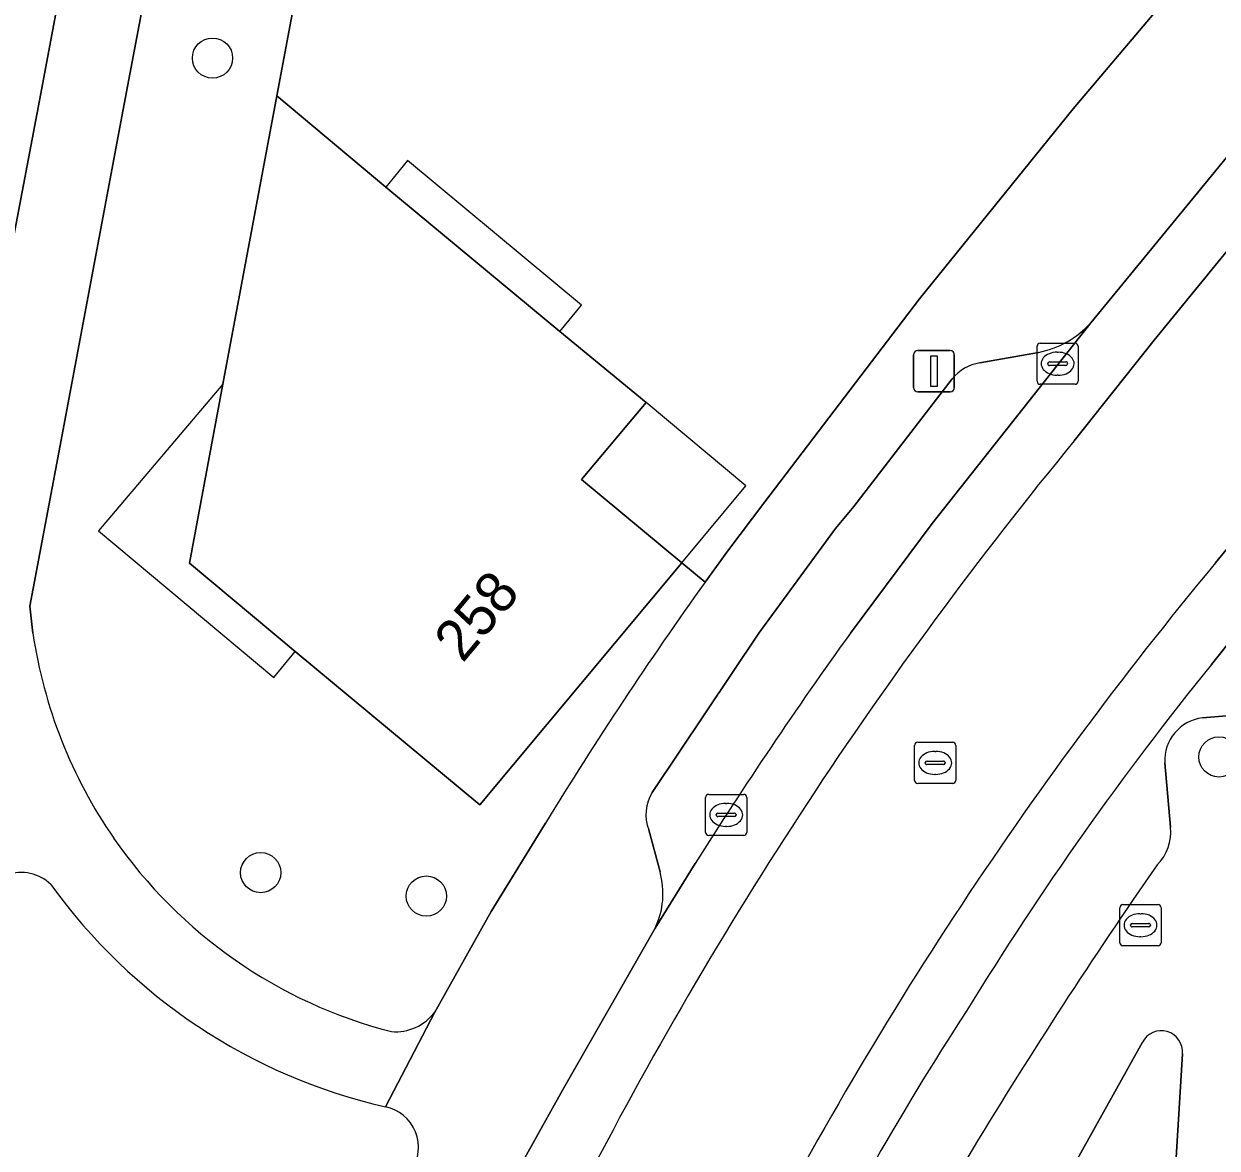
# Model space of a CAD drawing. Extents: x 160157 to 160921, y 381516 to 382045.
# Drawn here: x 160530.62 to 160559.64, y 381737.47 to 381764.83 of the extents above; entities that cross this region are included whole.
import ezdxf

# ---------------------------------------------------------------- set-up
doc = ezdxf.new("R2010")
doc.units = 0
for name, color, linetype in [('IMGEO_Boom', 7, 'Continuous'), ('IMGEO_Brandkraan', 7, 'Continuous'), ('IMGEO_Erf', 7, 'Continuous'), ('IMGEO_Groenvoorziening', 7, 'Continuous'), ('IMGEO_Kolk', 7, 'Continuous'), ('IMGEO_Lichtmast', 7, 'Continuous'), ('IMGEO_Muur', 7, 'Continuous'), ('IMGEO_Pand', 7, 'Continuous'), ('IMGEO_Pand_nummerreeks', 7, 'Continuous'), ('IMGEO_Pand_overbouw', 7, 'Continuous'), ('IMGEO_Parkeervlak_open', 7, 'Continuous'), ('IMGEO_Rijbaan_lokaal_gesloten', 7, 'Continuous'), ('IMGEO_Rijbaan_lokaal_open', 7, 'Continuous'), ('IMGEO_Rijbaan_regionaal_gesloten', 7, 'Continuous'), ('IMGEO_Rioolput', 7, 'Continuous'), ('IMGEO_Voetpad_open', 7, 'Continuous')]:
    doc.layers.add(name, color=color, linetype=linetype)

msp = doc.modelspace()

# ---------------------------------------------------------------- linework, layer by layer
at = {"layer": 'IMGEO_Boom'}
for centre in [(160535.206, 381763.995), (160559.686, 381746.988), (160536.378, 381744.173), (160540.407, 381743.603)]:
    msp.add_circle(centre, 0.489, dxfattribs=at)
at = {"layer": 'IMGEO_Brandkraan'}
for p, q in [((160557.276, 381742.468), (160557.276, 381743.32)), ((160557.351, 381743.394), (160558.203, 381743.394)), ((160558.277, 381743.32), (160558.277, 381742.468)), ((160557.764, 381743.174), (160557.789, 381743.174)), ((160557.535, 381742.888), (160557.535, 381742.9)), ((160557.973, 381742.851), (160557.575, 381742.851)), ((160557.578, 381742.937), (160557.976, 381742.937)), ((160558.019, 381742.9), (160558.019, 381742.888)), ((160557.787, 381742.614), (160557.762, 381742.614)), ((160558.203, 381742.394), (160557.351, 381742.394))]:
    msp.add_line(p, q, dxfattribs=at)
for points in [[(160557.276, 381742.468), (160557.276, 381743.32)], [(160557.351, 381743.394), (160558.203, 381743.394)], [(160558.277, 381743.32), (160558.277, 381742.468)], [(160558.203, 381742.394), (160557.351, 381742.394)]]:
    msp.add_lwpolyline(points, dxfattribs=at)
for centre, radius, start, end in [((160557.353, 381743.318), 0.0765, 91.552, 178.448), ((160557.353, 381743.318), 0.0765, 91.552, 178.448), ((160558.201, 381743.318), 0.0765, 1.552, 88.448), ((160558.201, 381743.318), 0.0765, 1.552, 88.448), ((160557.575, 381742.897), 0.0403, 85.8775, 175.7526), ((160557.572, 381742.887), 0.0366, 178.938, 274.7102), ((160557.976, 381742.894), 0.043, 264.8664, 352.4533), ((160557.98, 381742.899), 0.0386, 1.7309, 96.639), ((160557.353, 381742.47), 0.0765, 181.552, 268.448), ((160557.353, 381742.47), 0.0765, 181.552, 268.448), ((160558.201, 381742.47), 0.0765, 271.552, 358.448), ((160558.201, 381742.47), 0.0765, 271.552, 358.448)]:
    msp.add_arc(centre, radius, start, end, dxfattribs=at)
for centre, major_axis, ratio, start_param, end_param in [((160557.763, 381742.894), (-0.387, 0.002), 0.722429, 4.712389, 7.853982), ((160557.788, 381742.894), (-0.39, 0.002), 0.717154, 1.570796, 4.712389)]:
    msp.add_ellipse(centre, major_axis=major_axis, ratio=ratio, start_param=start_param, end_param=end_param, dxfattribs=at)
at = {"layer": 'IMGEO_Erf'}
msp.add_lwpolyline([(160539.559, 381777.945), (160536.769, 381763.076), (160539.423, 381760.856), (160543.658, 381757.346), (160545.757, 381755.618), (160544.18, 381753.74), (160546.621, 381751.714), (160547.187, 381751.244), (160547.737, 381752.007), (160548.643, 381753.199), (160552.4, 381758.139), (160556.143, 381762.763), (160556.812, 381763.555), (160559.232, 381766.417)], dxfattribs=at)
at = {"layer": 'IMGEO_Groenvoorziening'}
for points in [[(160537.22, 381749.558), (160534.647, 381751.702), (160535.455, 381756.063), (160536.769, 381763.076), (160539.559, 381777.945), (160538.044, 381779.218), (160536.414, 381780.659), (160535.155, 381773.997), (160533.001, 381762.573), (160531.549, 381754.827), (160530.76, 381750.659), (160530.838, 381750)], [(160547.187, 381751.244), (160546.621, 381751.714), (160541.708, 381745.82), (160537.22, 381749.558)], [(160540.611, 381740.781), (160541.983, 381743.231), (160543.304, 381745.379)], [(160557.825, 381740.047), (160556.011, 381736.788), (160556.763, 381736.375), (160556.207, 381735.389), (160555.472, 381735.795), (160553.785, 381732.792), (160551.845, 381729.26)], [(160558.374, 381732.854), (160558.795, 381739.761)]]:
    msp.add_lwpolyline(points, dxfattribs=at)
for centre, radius, start, end in [((160627.441, 381693.893), 98.64, 144.44965, 148.5362), ((160542.505, 381751.716), 11.792, 188.3662, 214.6331), ((160542.491, 381751.709), 11.777, 214.6422, 255.5732), ((160530.557, 381743.145), 1.03, 45.9388, 173.6939), ((160542.511, 381751.955), 13.835, 215.6825, 257.0609), ((160539.652, 381741.494), 1.195, 265.4295, 323.3601), ((160558.282, 381739.81), 0.515, 354.542, 152.6021), ((160539.22, 381737.493), 0.997, 325.0805, 78.8663)]:
    msp.add_arc(centre, radius, start, end, dxfattribs=at)
at = {"layer": 'IMGEO_Kolk'}
for p, q in [((160555.261, 381756.132), (160555.261, 381756.984)), ((160555.336, 381757.058), (160556.188, 381757.058)), ((160556.262, 381756.984), (160556.262, 381756.132)), ((160555.749, 381756.838), (160555.774, 381756.838)), ((160555.52, 381756.552), (160555.52, 381756.564)), ((160555.958, 381756.515), (160555.56, 381756.515)), ((160555.563, 381756.601), (160555.961, 381756.601)), ((160556.004, 381756.564), (160556.004, 381756.552)), ((160555.772, 381756.278), (160555.747, 381756.278)), ((160556.188, 381756.058), (160555.336, 381756.058)), ((160547.199, 381745.152), (160547.199, 381746.004)), ((160547.274, 381746.078), (160548.126, 381746.078)), ((160548.2, 381746.004), (160548.2, 381745.152)), ((160547.501, 381745.621), (160547.899, 381745.621)), ((160547.687, 381745.858), (160547.712, 381745.858)), ((160547.458, 381745.572), (160547.458, 381745.584)), ((160547.896, 381745.535), (160547.498, 381745.535)), ((160547.942, 381745.584), (160547.942, 381745.572)), ((160548.126, 381745.078), (160547.274, 381745.078)), ((160547.71, 381745.298), (160547.685, 381745.298))]:
    msp.add_line(p, q, dxfattribs=at)
for points in [[(160555.261, 381756.132), (160555.261, 381756.984)], [(160555.336, 381757.058), (160556.188, 381757.058)], [(160556.262, 381756.984), (160556.262, 381756.132)], [(160556.188, 381756.058), (160555.336, 381756.058)], [(160547.199, 381745.152), (160547.199, 381746.004)], [(160547.274, 381746.078), (160548.126, 381746.078)], [(160548.2, 381746.004), (160548.2, 381745.152)], [(160548.126, 381745.078), (160547.274, 381745.078)]]:
    msp.add_lwpolyline(points, dxfattribs=at)
for centre, radius, start, end in [((160555.338, 381756.982), 0.0765, 91.552, 178.448), ((160555.338, 381756.982), 0.0765, 91.552, 178.448), ((160556.186, 381756.982), 0.0765, 1.552, 88.448), ((160556.186, 381756.982), 0.0765, 1.552, 88.448), ((160555.56, 381756.561), 0.0403, 85.8775, 175.7526), ((160555.557, 381756.551), 0.0366, 178.938, 274.7102), ((160555.961, 381756.558), 0.043, 264.8664, 352.4533), ((160555.965, 381756.563), 0.0386, 1.7309, 96.639), ((160555.338, 381756.134), 0.0765, 181.552, 268.448), ((160555.338, 381756.134), 0.0765, 181.552, 268.448), ((160556.186, 381756.134), 0.0765, 271.552, 358.448), ((160556.186, 381756.134), 0.0765, 271.552, 358.448), ((160547.276, 381746.002), 0.0765, 91.552, 178.448), ((160547.276, 381746.002), 0.0765, 91.552, 178.448), ((160548.124, 381746.002), 0.0765, 1.552, 88.448), ((160548.124, 381746.002), 0.0765, 1.552, 88.448), ((160547.498, 381745.581), 0.0403, 85.8775, 175.7526), ((160547.903, 381745.583), 0.0386, 1.7309, 96.639), ((160547.495, 381745.571), 0.0366, 178.938, 274.7102), ((160547.899, 381745.578), 0.043, 264.8664, 352.4533), ((160547.276, 381745.154), 0.0765, 181.552, 268.448), ((160547.276, 381745.154), 0.0765, 181.552, 268.448), ((160548.124, 381745.154), 0.0765, 271.552, 358.448), ((160548.124, 381745.154), 0.0765, 271.552, 358.448)]:
    msp.add_arc(centre, radius, start, end, dxfattribs=at)
for centre, major_axis, ratio, start_param, end_param in [((160555.748, 381756.558), (-0.387, 0.002), 0.722429, 4.712389, 7.853982), ((160555.773, 381756.558), (-0.39, 0.002), 0.717154, 1.570796, 4.712389), ((160547.686, 381745.578), (-0.387, 0.002), 0.722429, 4.712389, 7.853982), ((160547.711, 381745.578), (-0.39, 0.002), 0.717154, 1.570796, 4.712389)]:
    msp.add_ellipse(centre, major_axis=major_axis, ratio=ratio, start_param=start_param, end_param=end_param, dxfattribs=at)
at = {"layer": 'IMGEO_Lichtmast'}
for p, q in [((160552.259, 381755.976), (160552.259, 381756.776)), ((160552.259, 381756.776), (160552.259, 381755.976)), ((160552.359, 381756.876), (160553.149, 381756.876)), ((160553.149, 381756.876), (160552.359, 381756.876)), ((160553.249, 381756.776), (160553.249, 381755.976)), ((160553.249, 381755.976), (160553.249, 381756.776)), ((160553.149, 381755.876), (160552.359, 381755.876)), ((160552.359, 381755.876), (160553.149, 381755.876))]:
    msp.add_line(p, q, dxfattribs=at)
msp.add_lwpolyline([(160552.679, 381756.751), (160552.829, 381756.751), (160552.829, 381756.001), (160552.679, 381756.001), (160552.679, 381756.751)], dxfattribs=at)
for centre, start, end in [((160552.359, 381756.776), 90, 180), ((160552.359, 381756.776), 90, 180), ((160553.149, 381756.776), 0, 90), ((160553.149, 381756.776), 360, 90), ((160552.359, 381755.976), 180, 270), ((160552.359, 381755.976), 180, 270), ((160553.149, 381755.976), 270, 0), ((160553.149, 381755.976), 270, 0)]:
    msp.add_arc(centre, 0.1, start, end, dxfattribs=at)
at = {"layer": 'IMGEO_Muur'}
msp.add_lwpolyline([(160539.559, 381777.945), (160536.769, 381763.076)], dxfattribs=at)
at = {"layer": 'IMGEO_Pand'}
msp.add_lwpolyline([(160543.658, 381757.346), (160539.423, 381760.856), (160536.769, 381763.076), (160535.455, 381756.063), (160534.647, 381751.702), (160537.22, 381749.558), (160541.708, 381745.82), (160546.621, 381751.714), (160544.18, 381753.74), (160545.757, 381755.618)], close=True, dxfattribs=at)
at = {"layer": 'IMGEO_Pand_overbouw'}
for points in [[(160539.423, 381760.856), (160543.658, 381757.346), (160544.179, 381757.981), (160539.946, 381761.505)], [(160537.22, 381749.558), (160534.647, 381751.702), (160535.455, 381756.063), (160532.435, 381752.487), (160536.695, 381748.923)], [(160546.621, 381751.714), (160548.178, 381753.589), (160545.757, 381755.618), (160544.18, 381753.74)]]:
    msp.add_lwpolyline(points, close=True, dxfattribs=at)
at = {"layer": 'IMGEO_Parkeervlak_open'}
for points in [[(160587.813, 381780.546), (160599.457, 381794.39), (160603.167, 381798.883), (160601.731, 381800.097), (160571.401, 381763.753), (160567.175, 381758.693), (160560.113, 381750), (160559.501, 381749.238)], [(160550.722, 381750), (160552.708, 381752.669), (160556.569, 381757.556)], [(160555.296, 381756.832), (160553.871, 381756.578)], [(160553.198, 381756.188), (160550.801, 381753.081), (160550.361, 381752.545), (160548.495, 381750), (160545.901, 381746.126)], [(160559.284, 381747.937), (160560.449, 381748.035)], [(160558.508, 381745.28), (160558.366, 381746.845)], [(160545.815, 381745.216), (160546.091, 381744.193)], [(160545.97, 381742.825), (160546.946, 381744.393)]]:
    msp.add_lwpolyline(points, dxfattribs=at)
for centre, radius, start, end in [((160554.856, 381759.087), 2.297, 281.0424, 318.2144), ((160554.037, 381755.516), 1.075, 98.8848, 141.2994), ((160638.25, 381686.98), 107.855, 144.24611, 147.83778), ((160621.002, 381699.491), 79.102, 141.03142, 148.50079), ((160559.408, 381746.901), 1.044, 96.8317, 183.0635), ((160546.801, 381745.582), 1.052, 148.8474, 200.3551), ((160557.409, 381745.154), 1.106, 314.2629, 6.5244), ((160544.229, 381743.668), 1.934, 334.1528, 15.7378), ((160665.269, 381669.95), 130.403, 145.20587, 148.81771), ((160616.65, 381699.761), 75.278, 146.94466, 153.91056), ((160642.221, 381685.451), 102.668, 149.55897, 154.04706)]:
    msp.add_arc(centre, radius, start, end, dxfattribs=at)
at = {"layer": 'IMGEO_Rijbaan_lokaal_gesloten'}
for points in [[(160556.164, 381754.68), (160558.112, 381757.129), (160560.755, 381760.365), (160581.539, 381785.212), (160597.19, 381803.934), (160596.045, 381804.906), (160595.807, 381805.107), (160595.401, 381804.621), (160589.126, 381797.112), (160588.465, 381796.32), (160588.699, 381796.124), (160587.352, 381794.513), (160562.011, 381764.214), (160561.758, 381763.877), (160556.569, 381757.556), (160552.708, 381752.669), (160550.722, 381750)], [(160559.501, 381749.238), (160560.113, 381750), (160567.175, 381758.693), (160571.401, 381763.753), (160601.731, 381800.097), (160600.729, 381800.991), (160582.713, 381779.526), (160568.843, 381763.002), (160559.601, 381751.709)], [(160546.946, 381744.393), (160545.97, 381742.825), (160543.709, 381738.866), (160540.908, 381733.824)]]:
    msp.add_lwpolyline(points, dxfattribs=at)
for centre, radius, start, end in [((160635.278, 381689.632), 102.422, 140.57288, 152.83712), ((160632.422, 381691.188), 94.687, 140.2702, 153.23003), ((160638.25, 381686.98), 107.855, 144.24611, 147.83778), ((160621.002, 381699.491), 79.102, 141.03142, 148.50079), ((160616.65, 381699.761), 75.278, 146.94466, 153.91056)]:
    msp.add_arc(centre, radius, start, end, dxfattribs=at)
at = {"layer": 'IMGEO_Rijbaan_lokaal_open'}
for points in [[(160568.843, 381763.002), (160582.713, 381779.526), (160600.729, 381800.991), (160597.19, 381803.934), (160581.539, 381785.212), (160560.755, 381760.365), (160558.112, 381757.129), (160556.164, 381754.68)], [(160559.601, 381751.709), (160568.843, 381763.002)]]:
    msp.add_lwpolyline(points, dxfattribs=at)
for centre, radius, start, end in [((160635.278, 381689.632), 102.422, 140.57288, 152.83712), ((160632.422, 381691.188), 94.687, 140.2702, 153.23003)]:
    msp.add_arc(centre, radius, start, end, dxfattribs=at)
at = {"layer": 'IMGEO_Rijbaan_regionaal_gesloten'}
msp.add_lwpolyline([(160528.299, 381748.554), (160528.561, 381750), (160529.214, 381753.603), (160531.031, 381763.137), (160531.658, 381766.473), (160532.282, 381769.787), (160534.195, 381779.861), (160534.361, 381783.239), (160534.845, 381787.255), (160535.72, 381795.222), (160536.596, 381803.188)], dxfattribs=at)
at = {"layer": 'IMGEO_Rioolput'}
for p, q in [((160552.283, 381746.418), (160552.283, 381747.27)), ((160552.358, 381747.344), (160553.21, 381747.344)), ((160552.771, 381747.124), (160552.796, 381747.124)), ((160553.284, 381747.27), (160553.284, 381746.418)), ((160552.542, 381746.838), (160552.542, 381746.85)), ((160552.98, 381746.801), (160552.582, 381746.801)), ((160552.585, 381746.887), (160552.983, 381746.887)), ((160553.026, 381746.85), (160553.026, 381746.838)), ((160552.794, 381746.564), (160552.769, 381746.564)), ((160553.21, 381746.344), (160552.358, 381746.344))]:
    msp.add_line(p, q, dxfattribs=at)
for points in [[(160552.283, 381746.418), (160552.283, 381747.27)], [(160552.358, 381747.344), (160553.21, 381747.344)], [(160553.284, 381747.27), (160553.284, 381746.418)], [(160553.21, 381746.344), (160552.358, 381746.344)]]:
    msp.add_lwpolyline(points, dxfattribs=at)
for centre, radius, start, end in [((160552.36, 381747.268), 0.0765, 91.552, 178.448), ((160552.36, 381747.268), 0.0765, 91.552, 178.448), ((160553.208, 381747.268), 0.0765, 1.552, 88.448), ((160553.208, 381747.268), 0.0765, 1.552, 88.448), ((160552.582, 381746.847), 0.0403, 85.8775, 175.7526), ((160552.579, 381746.837), 0.0366, 178.938, 274.7102), ((160552.983, 381746.844), 0.043, 264.8664, 352.4533), ((160552.987, 381746.849), 0.0386, 1.7309, 96.639), ((160552.36, 381746.42), 0.0765, 181.552, 268.448), ((160552.36, 381746.42), 0.0765, 181.552, 268.448), ((160553.208, 381746.42), 0.0765, 271.552, 358.448), ((160553.208, 381746.42), 0.0765, 271.552, 358.448)]:
    msp.add_arc(centre, radius, start, end, dxfattribs=at)
for centre, major_axis, ratio, start_param, end_param in [((160552.77, 381746.844), (-0.387, 0.002), 0.722429, 4.712389, 7.853982), ((160552.795, 381746.844), (-0.39, 0.002), 0.717154, 1.570796, 4.712389)]:
    msp.add_ellipse(centre, major_axis=major_axis, ratio=ratio, start_param=start_param, end_param=end_param, dxfattribs=at)
at = {"layer": 'IMGEO_Voetpad_open'}
for points in [[(160540.822, 381821.339), (160539.588, 381811.172), (160538.964, 381806.709), (160537.65, 381798.47), (160536.108, 381789.935), (160534.195, 381779.861), (160532.282, 381769.787), (160531.658, 381766.473), (160531.031, 381763.137), (160529.214, 381753.603), (160528.561, 381750), (160528.299, 381748.554)], [(160587.941, 381807.827), (160580.593, 381798.887), (160569.786, 381785.666), (160572.924, 381783.093), (160566.256, 381774.976), (160559.232, 381766.417), (160556.812, 381763.555), (160556.143, 381762.763), (160552.4, 381758.139), (160548.643, 381753.199), (160547.737, 381752.007), (160547.187, 381751.244)], [(160530.838, 381750), (160530.76, 381750.659), (160531.549, 381754.827), (160533.001, 381762.573), (160535.155, 381773.997), (160536.414, 381780.659)], [(160556.569, 381757.556), (160561.758, 381763.877), (160562.011, 381764.214)], [(160553.871, 381756.578), (160555.296, 381756.832)], [(160545.901, 381746.126), (160548.495, 381750), (160550.361, 381752.545), (160550.801, 381753.081), (160553.198, 381756.188)], [(160572.841, 381708.802), (160571.401, 381709.981), (160559.681, 381719.582), (160561.169, 381743.908), (160560.449, 381748.035), (160559.284, 381747.937)], [(160558.366, 381746.845), (160558.508, 381745.28)], [(160543.304, 381745.379), (160541.983, 381743.231), (160540.611, 381740.781), (160539.413, 381738.471)], [(160546.091, 381744.193), (160545.815, 381745.216)], [(160540.908, 381733.824), (160543.709, 381738.866), (160545.97, 381742.825)], [(160539.413, 381738.471), (160540.611, 381740.781)], [(160551.845, 381729.26), (160553.785, 381732.792), (160555.472, 381735.795), (160556.207, 381735.389), (160556.763, 381736.375), (160556.011, 381736.788), (160557.825, 381740.047)], [(160558.795, 381739.761), (160558.374, 381732.854)]]:
    msp.add_lwpolyline(points, dxfattribs=at)
for centre, radius, start, end in [((160554.856, 381759.087), 2.297, 281.0424, 318.2144), ((160554.037, 381755.516), 1.075, 98.8848, 141.2994), ((160627.441, 381693.893), 98.64, 144.44965, 148.5362), ((160542.505, 381751.716), 11.792, 188.3662, 214.6331), ((160559.408, 381746.901), 1.044, 96.8317, 183.0635), ((160546.801, 381745.582), 1.052, 148.8474, 200.3551), ((160557.409, 381745.154), 1.106, 314.2629, 6.5244), ((160542.491, 381751.709), 11.777, 214.6422, 255.5732), ((160530.557, 381743.145), 1.03, 45.9388, 173.6939), ((160544.229, 381743.668), 1.934, 334.1528, 15.7378), ((160665.269, 381669.95), 130.403, 145.20587, 148.81771), ((160542.511, 381751.955), 13.835, 215.6825, 257.0609), ((160539.652, 381741.494), 1.195, 265.4295, 323.3601), ((160558.282, 381739.81), 0.515, 354.542, 152.6021), ((160539.22, 381737.493), 0.997, 325.0805, 78.8663), ((160642.221, 381685.451), 102.668, 149.55897, 154.04706)]:
    msp.add_arc(centre, radius, start, end, dxfattribs=at)

# ---------------------------------------------------------------- texts
at = {"layer": 'IMGEO_Pand_nummerreeks'}
msp.add_text('258', height=1, rotation=50.1891, dxfattribs=at).set_placement((160541.291, 381749.255))

doc.saveas('drawing.dxf')
